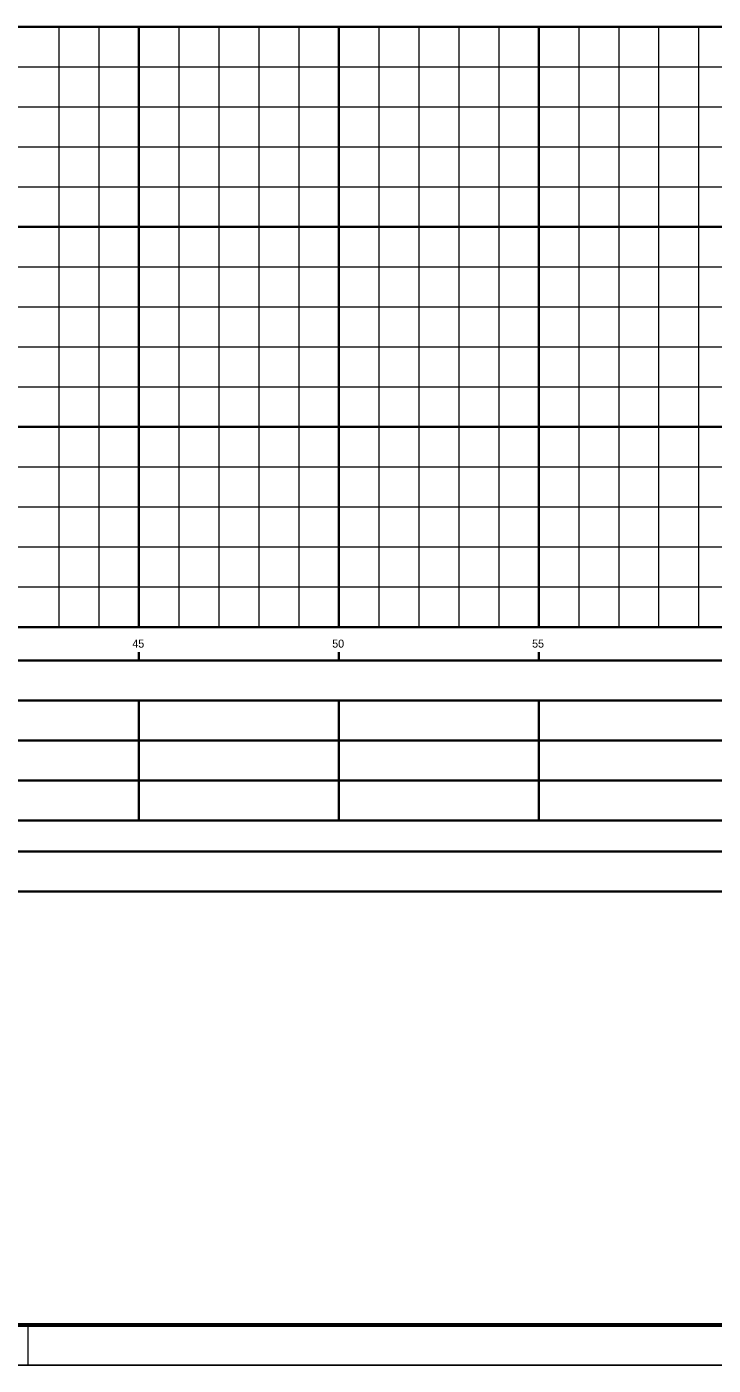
# Model space of a CAD drawing. Extents: x 949 to 2631, y -1701 to -513.
# Drawn here: x 1910 to 2254, y -1701 to -1032 of the extents above; entities that cross this region are included whole.
import ezdxf
from ezdxf.enums import TextEntityAlignment as Align

# ---------------------------------------------------------------- set-up
doc = ezdxf.new("R2010")
doc.units = 0
doc.header["$LTSCALE"] = 1.2
for name, color, linetype, lineweight in [('1', 7, 'Continuous', 13), ('35', 7, 'Continuous', 35), ('5', 7, 'Continuous', 13), ('6', 7, 'Continuous', 60), ('7', 7, 'Continuous', 35)]:
    doc.layers.add(name, color=color, linetype=linetype, lineweight=lineweight)

msp = doc.modelspace()

# ---------------------------------------------------------------- linework, layer by layer
at = {"layer": '35'}
msp.add_line((1066.405, -1231.771), (2466.405, -1231.771), dxfattribs=at)
at = {"layer": '5'}
for p, q in [((1066.405, -1051.771), (2566.405, -1051.771)), ((1066.405, -1071.771), (2566.405, -1071.771)), ((1066.405, -1091.771), (2566.405, -1091.771)), ((1066.405, -1111.771), (2566.405, -1111.771)), ((1066.405, -1151.771), (2566.405, -1151.771)), ((1066.405, -1171.771), (2566.405, -1171.771)), ((1066.405, -1191.771), (2566.405, -1191.771)), ((1066.405, -1211.771), (2566.405, -1211.771)), ((1066.405, -1251.771), (2566.405, -1251.771)), ((1066.405, -1271.771), (2566.405, -1271.771)), ((1066.405, -1291.771), (2566.405, -1291.771)), ((1066.405, -1311.771), (2566.405, -1311.771)), ((1910.926, -1700.728), (1910.926, -1680.728)), ((948.926, -1700.728), (2623.017, -1700.728)), ((948.926, -1700.728), (2630.926, -1700.728)), ((948.926, -1700.728), (2630.926, -1700.728))]:
    msp.add_line(p, q, dxfattribs=at)
msp.add_lwpolyline([(948.926, -1700.728), (2630.926, -1700.728), (948.926, -1700.728)], dxfattribs=at)
at = {"layer": '6'}
msp.add_line((2610.926, -1680.728), (998.926, -1680.728), dxfattribs=at)
at = {"layer": '7'}
for p, q in [((1066.405, -1031.771), (2566.405, -1031.771)), ((1966.405, -1031.771), (1966.405, -1331.771)), ((2066.405, -1031.771), (2066.405, -1331.771)), ((2166.405, -1031.771), (2166.405, -1331.771)), ((1066.405, -1131.771), (2566.405, -1131.771)), ((1066.405, -1231.771), (2566.405, -1231.771)), ((2566.405, -1331.771), (1007.352, -1331.771)), ((1966.405, -1344.336), (1966.405, -1348.501)), ((2066.405, -1344.336), (2066.405, -1348.501)), ((2166.405, -1344.336), (2166.405, -1348.501)), ((1064.486, -1348.501), (2566.405, -1348.501)), ((1064.486, -1368.501), (2566.405, -1368.501)), ((1966.405, -1368.501), (1966.405, -1428.501)), ((2066.396, -1368.501), (2566.405, -1368.501)), ((2066.405, -1368.501), (2066.405, -1428.501)), ((2166.405, -1368.501), (2166.405, -1428.501)), ((1064.486, -1388.501), (2566.405, -1388.501)), ((1064.486, -1408.501), (2566.405, -1408.501)), ((1064.486, -1428.501), (2566.405, -1428.501)), ((1064.486, -1443.951), (2566.405, -1443.951)), ((1064.486, -1463.951), (2566.405, -1463.951))]:
    msp.add_line(p, q, dxfattribs=at)
at = {"layer": '7', "lineweight": 13}
for p, q in [((1926.405, -1031.771), (1926.405, -1331.771)), ((1946.405, -1031.771), (1946.405, -1331.771)), ((1986.405, -1031.771), (1986.405, -1331.771)), ((2006.405, -1031.771), (2006.405, -1331.771)), ((2026.405, -1031.771), (2026.405, -1331.771)), ((2046.405, -1031.771), (2046.405, -1331.771)), ((2086.405, -1031.771), (2086.405, -1331.771)), ((2106.405, -1031.771), (2106.405, -1331.771)), ((2126.405, -1031.771), (2126.405, -1331.771)), ((2146.405, -1031.771), (2146.405, -1331.771)), ((2186.405, -1031.771), (2186.405, -1331.771)), ((2206.405, -1031.771), (2206.405, -1331.771)), ((2226.405, -1031.771), (2226.405, -1331.771)), ((2246.405, -1031.771), (2246.405, -1331.771))]:
    msp.add_line(p, q, dxfattribs=at)

# ---------------------------------------------------------------- texts
at = {"layer": '1'}
for s, p in [('45', (1966.076, -1342.071)), ('50', (2066.076, -1342.071)), ('55', (2166.076, -1342.071))]:
    msp.add_text(s, height=4, dxfattribs=at).set_placement(p, align=Align.CENTER)

doc.saveas('drawing.dxf')
